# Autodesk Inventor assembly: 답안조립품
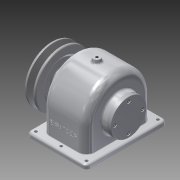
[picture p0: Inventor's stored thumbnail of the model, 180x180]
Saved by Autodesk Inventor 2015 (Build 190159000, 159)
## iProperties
Created: 2015-09
Part Number: 답안조립품
Document SubType Name: Assembly
Designer: PHO-1
Author: PHO-1
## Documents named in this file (14)
- C:\Users\PHO-1\Desktop\450907V1015\답안조립품.iam
- C:\Users\PHO-1\Desktop\450907V1015\본체.ipt
- C:\Users\PHO-1\Desktop\450907V1015\뒤커버.ipt
- C:\Users\PHO-1\Desktop\450907V1015\앞커버.ipt
- C:\Users\PHO-1\Desktop\450907V1015\볼트 M3 x 8.ipt
- C:\Users\PHO-1\Desktop\450907V1015\볼트 M3 x 10.ipt
- C:\Users\PHO-1\Desktop\450907V1015\베어링 6203.ipt
- C:\Users\PHO-1\Desktop\450907V1015\오일 실 17 32 8.ipt
- C:\Users\PHO-1\Desktop\450907V1015\축.ipt
- C:\Users\PHO-1\Desktop\450907V1015\키 - 5 x 5 x 18.ipt
- C:\Users\PHO-1\Desktop\450907V1015\키 - 6 x 6 x 22.ipt
- C:\Users\PHO-1\Desktop\450907V1015\스퍼기어.ipt
- C:\Users\PHO-1\Desktop\450907V1015\멈춤나사 - M4x10.ipt
- C:\Users\PHO-1\Desktop\450907V1015\V-벨트풀리.ipt
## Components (9 placed, 3 different names)
1. V-벨트풀리:1 — 각도:4
2. ISO 4762 M3 x 8:1 — 각도:1
3. ISO 4762 M3 x 8:2
4. ISO 4762 M3 x 8:3
5. ISO 4762 M3 x 8:4
6. ISO 4762 M3 x 10:1 — 각도:2
7. ISO 4762 M3 x 10:2
8. ISO 4762 M3 x 10:3
9. ISO 4762 M3 x 10:4
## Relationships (3: Angle 3)
- 각도:1 [Angle]: ISO 4762 M3 x 8:1
- 각도:2 [Angle]: ISO 4762 M3 x 10:1
- 각도:4 [Angle]: V-벨트풀리:1
